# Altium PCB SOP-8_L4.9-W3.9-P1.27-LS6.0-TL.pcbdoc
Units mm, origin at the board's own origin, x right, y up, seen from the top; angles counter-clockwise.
Board outline 20.16 x 18.04 mm, 2 copper layers (Top Layer, Bottom Layer), stack 0 mm thick; 1 components, 0 nets, 8 pads, 0 vias.
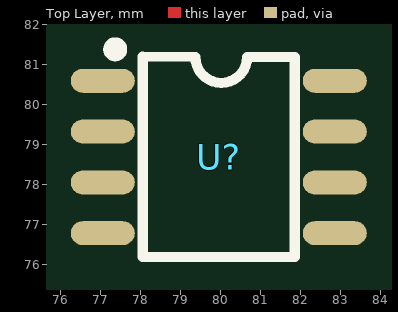
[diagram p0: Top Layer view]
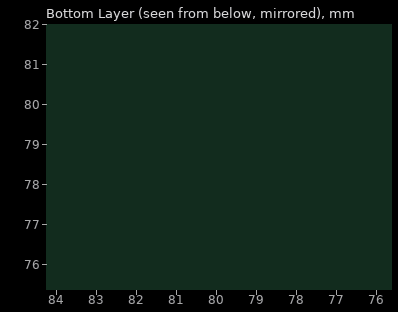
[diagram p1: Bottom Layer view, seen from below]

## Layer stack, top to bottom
Top Layer: signal copper (thickness not stored)
Bottom Layer: signal copper (thickness not stored)

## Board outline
90.006,69.85 69.85,69.85 69.85,87.891 90.006,87.891

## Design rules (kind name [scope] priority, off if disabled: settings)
PasteMaskExpansion "Paste Mask Expansion" [All] p1: expansion=0
SolderMaskExpansion "Solder Mask Expansion" [IsVia] p1: expansion=-25.4 istentingtop=TRUE
SolderMaskExpansion "Solder Mask Expansion" [All] p2: expansion=0.051 istentingtop=FALSE

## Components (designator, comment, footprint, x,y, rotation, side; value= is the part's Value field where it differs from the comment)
U? "" SOP-8_L4.9-W3.9-P1.27-LS6.0-TL 79.956,78.7 r0 top

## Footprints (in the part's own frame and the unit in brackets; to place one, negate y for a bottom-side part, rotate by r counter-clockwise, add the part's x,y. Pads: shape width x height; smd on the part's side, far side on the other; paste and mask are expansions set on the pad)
SOP-8_L4.9-W3.9-P1.27-LS6.0-TL [mm]
  oval 1.6x0.6 smd: 1(-2.9,1.905) 2(-2.9,0.635) 3(-2.9,-0.635) 4(-2.9,-1.905) 5(2.9,-1.905) 6(2.9,-0.635) 7(2.9,0.635) 8(2.9,1.905)
  silkscreen extent -2.74,-2.5 1.9,2.84

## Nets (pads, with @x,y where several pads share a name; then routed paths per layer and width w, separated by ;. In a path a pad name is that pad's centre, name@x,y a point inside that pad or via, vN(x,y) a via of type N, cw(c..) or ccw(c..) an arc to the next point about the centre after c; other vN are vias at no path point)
pads on no net: U?.1 U?.2 U?.3 U?.4 U?.5 U?.6 U?.7 U?.8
